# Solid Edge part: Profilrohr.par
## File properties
Username: bmolnar
Dokumentum tartalom típus: 0
Author: bmolnar
Last saved by: bmolnar
Revision: 97
Sűrűség: 0,000 kg/m^3
Pontosság: 0,990
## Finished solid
Body 1: solid body, 115 faces, 338 edges, 224 vertices.
  Faces by surface: cylinder 59, plane 56
  Edges by curve: line 220, circle 118
Bounding box of the edges (mm): 113.500 x 113.500 x 428.000, from (-56.75, -56.75, -411.5) to (56.75, 56.75, 16.5).
Cylindrical faces by radius (mm): R0.15 x24, R0.25 x24, R1 x4, R12.25 x4, R35 x2, R50 x1
Planar faces by outward normal: +x 13, +y 14, +z 1, -x 13, -y 14, -z 1
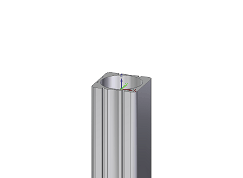
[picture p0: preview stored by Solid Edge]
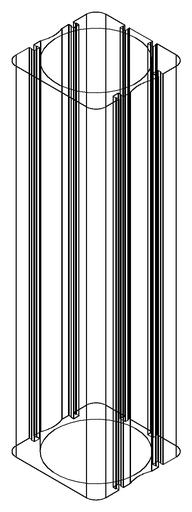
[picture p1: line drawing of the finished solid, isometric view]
